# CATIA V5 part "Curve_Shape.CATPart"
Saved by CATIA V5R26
Part number: Curve_Shape
Bounding box of the stored display mesh (mm): x 779.468 to 1382.914, y -778.323 to -669.675, z 414.34 to 524.862
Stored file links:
  D:\LinkedIn Learning\NURBS\CATIA\Class Parts\Curve_Shape.CATPart
  D:\LinkedIn Learning\NURBS\CATIA\Class Parts\Arm_Rest-Step-2.CATPart
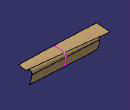
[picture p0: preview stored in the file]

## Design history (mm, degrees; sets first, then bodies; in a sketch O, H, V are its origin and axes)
AxisSystem1: origin (0, 0, 0), X (1, 0, 0), Y (0, 1, 0), Z (0, 0, 1)
Set1
  DatumSurface1
  DatumSurface2
  StTopoTypeFeature1 "CATStTopoTypeFeatureName": nls://CATStFeaturesStartUpsNLS/TopoVarRadiCke 35, nls://CATStFeaturesStartUpsNLS/TopoVarRadiCke 15
  Intersect1: ToIntersect1 DatumSurface2, ToIntersect2 DatumSurface1
  Plane1: type Normal, Curve Intersect1, Ratio 0
  Intersect2: ToIntersect1 StTopoTypeFeature1, ToIntersect2 Plane1
Body1 (main body)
